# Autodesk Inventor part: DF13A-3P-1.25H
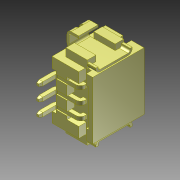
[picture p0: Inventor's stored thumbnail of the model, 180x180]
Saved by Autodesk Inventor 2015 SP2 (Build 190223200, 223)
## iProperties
Created: 2015-09
Part Number: DF13A-3P-1.25H
Material: Allgemein
Document SubType Name: Modeling
Designer: rYan
Density: 1 g/cm^3
Appearance: Vorgabe
Author: rYan
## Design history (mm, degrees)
node "DF13A-3P-1.25H"
node "Volumenkörper1"
node "Basis1"
